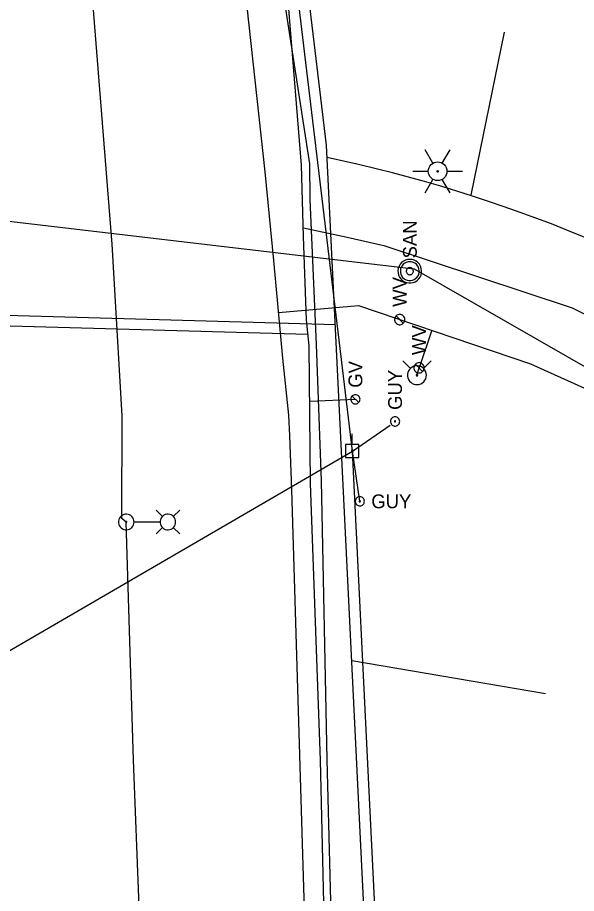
# Model space of a CAD drawing. Extents: x 600849 to 606371, y 330010 to 403088.
# Drawn here: x 604911.1 to 605066.9, y 335171 to 335415.1 of the extents above; entities that cross this region are included whole.
import ezdxf

# ---------------------------------------------------------------- set-up
doc = ezdxf.new("R2010")
doc.units = 0
for name, color, linetype in [('E_LTG', 7, 'Continuous'), ('E_LTG_CID', 7, 'Continuous'), ('E_UTL_EGuyWire', 7, 'Continuous'), ('E_UTL_EPowerPole', 7, 'Continuous'), ('E_UTL_G', 7, 'Continuous'), ('E_UTL_G_UG', 7, 'Continuous'), ('E_UTL_Overhead', 7, 'Continuous'), ('E_UTL_SAN', 7, 'Continuous'), ('E_UTL_SAN_UG', 7, 'Continuous'), ('E_UTL_W', 7, 'Continuous'), ('E_UTL_W_UG', 7, 'Continuous'), ('E_UTL_WHydrant', 7, 'Continuous')]:
    doc.layers.add(name, color=color, linetype=linetype)

msp = doc.modelspace()

# ---------------------------------------------------------------- linework, layer by layer
at = {"layer": 'E_LTG'}
for points in [[(605026.92, 335374.51), (605024.75, 335378.26)], [(605029.52, 335374.51), (605031.68, 335378.26)], [(605021.29, 335372.26), (605025.62, 335372.26)], [(605030.82, 335372.26), (605035.15, 335372.26)], [(605024.75, 335366.26), (605026.92, 335370.01)], [(605031.68, 335366.26), (605029.52, 335370.01)], [(604951.46, 335276.05), (604949.68, 335277.83)], [(604954.51, 335276.05), (604956.28, 335277.83)], [(604943.56, 335274.53), (604943.52, 335274.94), (604943.4, 335275.34), (604943.21, 335275.71), (604942.95, 335276.03), (604942.64, 335276.3), (604942.28, 335276.51), (604941.89, 335276.64), (604941.48, 335276.7), (604941.07, 335276.68), (604940.67, 335276.59), (604940.29, 335276.41), (604939.96, 335276.17), (604939.67, 335275.87), (604939.45, 335275.53), (604939.29, 335275.14), (604939.21, 335274.74), (604939.21, 335274.32), (604939.29, 335273.92), (604939.45, 335273.53), (604939.67, 335273.18), (604939.96, 335272.89), (604940.29, 335272.65), (604940.67, 335272.47), (604941.07, 335272.38), (604941.48, 335272.36), (604941.89, 335272.42), (604942.28, 335272.55), (604942.64, 335272.76), (604942.95, 335273.03), (604943.21, 335273.35), (604943.4, 335273.72), (604943.52, 335274.12), (604943.56, 335274.53)], [(604955.16, 335274.53), (604955.12, 335274.94), (604955, 335275.34), (604954.81, 335275.71), (604954.56, 335276.03), (604954.25, 335276.3), (604953.89, 335276.51), (604953.5, 335276.64), (604953.09, 335276.7), (604952.67, 335276.68), (604952.27, 335276.59), (604951.9, 335276.41), (604951.56, 335276.17), (604951.27, 335275.87), (604951.05, 335275.53), (604950.9, 335275.14), (604950.82, 335274.74), (604950.82, 335274.32), (604950.9, 335273.92), (604951.05, 335273.53), (604951.27, 335273.18), (604951.56, 335272.89), (604951.9, 335272.65), (604952.27, 335272.47), (604952.67, 335272.38), (604953.09, 335272.36), (604953.5, 335272.42), (604953.89, 335272.55), (604954.25, 335272.76), (604954.56, 335273.03), (604954.81, 335273.35), (604955, 335273.72), (604955.12, 335274.12), (604955.16, 335274.53)], [(604941.55, 335274.53), (604941.54, 335274.56), (604941.53, 335274.59), (604941.52, 335274.62), (604941.5, 335274.64), (604941.48, 335274.66), (604941.45, 335274.68), (604941.42, 335274.69), (604941.39, 335274.7), (604941.36, 335274.69), (604941.33, 335274.69), (604941.3, 335274.67), (604941.27, 335274.66), (604941.25, 335274.63), (604941.23, 335274.61), (604941.22, 335274.58), (604941.21, 335274.55), (604941.21, 335274.51), (604941.22, 335274.48), (604941.23, 335274.45), (604941.25, 335274.43), (604941.27, 335274.4), (604941.3, 335274.39), (604941.33, 335274.37), (604941.36, 335274.36), (604941.39, 335274.36), (604941.42, 335274.37), (604941.45, 335274.38), (604941.48, 335274.39), (604941.5, 335274.41), (604941.52, 335274.44), (604941.53, 335274.47), (604941.54, 335274.5), (604941.55, 335274.53)], [(604950.77, 335274.53), (604943.59, 335274.53)], [(604951.46, 335273.01), (604949.68, 335271.23)], [(604954.51, 335273.01), (604956.28, 335271.23)]]:
    msp.add_lwpolyline(points, dxfattribs=at)
for radius in [2.6, 2.6, 2.6, 0.217]:
    msp.add_circle((605028.22, 335372.26), radius, dxfattribs=at)
at = {"layer": 'E_LTG_CID'}
msp.add_lwpolyline([(604969.99, 334606.09), (604967.03, 334670.29), (604963.28, 334734.35), (604962.55, 334735.4), (604960.49, 334790.4), (604957.1, 334864.55), (604955.09, 334914.72), (604953.95, 334915.4), (604951.63, 334970.04), (604948.08, 335053.71), (604947.83, 335094), (604947.12, 335095.14), (604944.98, 335167.5), (604943.36, 335208.16), (604941.38, 335274.53), (604940.11, 335275.5), (604940.27, 335304.13), (604937.49, 335351.94), (604930.99, 335433.63), (604929.86, 335454.1), (604928.76, 335455.44), (604919.1, 335533.39), (604912.51, 335573.53), (604907.99, 335610.09)], dxfattribs=at)
at = {"layer": 'E_UTL_EGuyWire'}
for p, q in [((605004.43, 335294.31), (605014.98, 335301.52)), ((605006.51, 335280.3), (605004.43, 335294.31))]:
    msp.add_line(p, q, dxfattribs=at)
for points in [[(605016.35, 335303.84), (605016.11, 335303.82), (605015.87, 335303.75), (605015.66, 335303.64), (605015.46, 335303.49), (605015.3, 335303.3), (605015.18, 335303.09), (605015.1, 335302.86), (605015.07, 335302.62), (605015.08, 335302.38), (605015.14, 335302.14), (605015.24, 335301.92), (605015.38, 335301.72), (605015.56, 335301.55), (605015.76, 335301.42), (605015.99, 335301.33), (605016.23, 335301.28), (605016.47, 335301.28), (605016.71, 335301.33), (605016.94, 335301.42), (605017.14, 335301.55), (605017.32, 335301.72), (605017.46, 335301.92), (605017.56, 335302.14), (605017.62, 335302.38), (605017.63, 335302.62), (605017.6, 335302.86), (605017.52, 335303.09), (605017.4, 335303.3), (605017.24, 335303.49), (605017.04, 335303.64), (605016.83, 335303.75), (605016.59, 335303.82), (605016.35, 335303.84)], [(605016.35, 335302.72), (605016.32, 335302.72), (605016.29, 335302.71), (605016.26, 335302.69), (605016.24, 335302.68), (605016.22, 335302.65), (605016.2, 335302.63), (605016.19, 335302.6), (605016.19, 335302.57), (605016.19, 335302.54), (605016.2, 335302.51), (605016.21, 335302.48), (605016.23, 335302.45), (605016.25, 335302.43), (605016.28, 335302.42), (605016.3, 335302.41), (605016.33, 335302.4), (605016.37, 335302.4), (605016.4, 335302.41), (605016.42, 335302.42), (605016.45, 335302.43), (605016.47, 335302.45), (605016.49, 335302.48), (605016.5, 335302.51), (605016.51, 335302.54), (605016.51, 335302.57), (605016.51, 335302.6), (605016.5, 335302.63), (605016.48, 335302.65), (605016.46, 335302.68), (605016.44, 335302.69), (605016.41, 335302.71), (605016.38, 335302.72), (605016.35, 335302.72)], [(605007.79, 335280.3), (605007.77, 335280.54), (605007.7, 335280.78), (605007.59, 335280.99), (605007.44, 335281.19), (605007.25, 335281.34), (605007.04, 335281.47), (605006.81, 335281.55), (605006.57, 335281.58), (605006.33, 335281.57), (605006.09, 335281.51), (605005.87, 335281.41), (605005.67, 335281.27), (605005.5, 335281.09), (605005.37, 335280.89), (605005.28, 335280.66), (605005.23, 335280.42), (605005.23, 335280.18), (605005.28, 335279.94), (605005.37, 335279.71), (605005.5, 335279.51), (605005.67, 335279.33), (605005.87, 335279.19), (605006.09, 335279.09), (605006.33, 335279.03), (605006.57, 335279.02), (605006.81, 335279.05), (605007.04, 335279.13), (605007.25, 335279.25), (605007.44, 335279.41), (605007.59, 335279.61), (605007.7, 335279.82), (605007.77, 335280.06), (605007.79, 335280.3)], [(605006.67, 335280.3), (605006.67, 335280.33), (605006.66, 335280.36), (605006.64, 335280.39), (605006.63, 335280.41), (605006.6, 335280.43), (605006.58, 335280.45), (605006.55, 335280.46), (605006.52, 335280.46), (605006.49, 335280.46), (605006.46, 335280.45), (605006.43, 335280.44), (605006.4, 335280.42), (605006.38, 335280.4), (605006.37, 335280.37), (605006.36, 335280.34), (605006.35, 335280.31), (605006.35, 335280.28), (605006.36, 335280.25), (605006.37, 335280.23), (605006.38, 335280.2), (605006.4, 335280.18), (605006.43, 335280.16), (605006.46, 335280.15), (605006.49, 335280.14), (605006.52, 335280.14), (605006.55, 335280.14), (605006.58, 335280.15), (605006.6, 335280.17), (605006.63, 335280.19), (605006.64, 335280.21), (605006.66, 335280.24), (605006.67, 335280.27), (605006.67, 335280.3)]]:
    msp.add_lwpolyline(points, dxfattribs=at)
at = {"layer": 'E_UTL_EPowerPole'}
for points in [[(605004.4, 335296.15), (605004.4, 335299.06)], [(605006.24, 335296.15), (605002.55, 335296.15)], [(605002.55, 335296.15), (605002.55, 335292.46)], [(605004.67, 335294.31), (605004.66, 335294.35), (605004.65, 335294.4), (605004.63, 335294.44), (605004.6, 335294.47), (605004.57, 335294.5), (605004.53, 335294.53), (605004.49, 335294.54), (605004.44, 335294.55), (605004.4, 335294.55), (605004.35, 335294.53), (605004.31, 335294.52), (605004.27, 335294.49), (605004.24, 335294.46), (605004.22, 335294.42), (605004.2, 335294.38), (605004.19, 335294.33), (605004.19, 335294.29), (605004.2, 335294.24), (605004.22, 335294.2), (605004.24, 335294.16), (605004.27, 335294.13), (605004.31, 335294.1), (605004.35, 335294.08), (605004.4, 335294.07), (605004.44, 335294.07), (605004.49, 335294.08), (605004.53, 335294.09), (605004.57, 335294.12), (605004.6, 335294.14), (605004.63, 335294.18), (605004.65, 335294.22), (605004.66, 335294.26), (605004.67, 335294.31)], [(605006.24, 335292.46), (605006.24, 335296.15)], [(605002.55, 335292.46), (605006.24, 335292.46)]]:
    msp.add_lwpolyline(points, dxfattribs=at)
at = {"layer": 'E_UTL_G'}
for points in [[(605005.29, 335310.01), (605005.05, 335309.99), (605004.81, 335309.92), (605004.6, 335309.81), (605004.4, 335309.66), (605004.24, 335309.47), (605004.12, 335309.26), (605004.04, 335309.03), (605004.01, 335308.79), (605004.02, 335308.55), (605004.08, 335308.31), (605004.18, 335308.09), (605004.32, 335307.89), (605004.5, 335307.72), (605004.7, 335307.59), (605004.93, 335307.5), (605005.17, 335307.45), (605005.41, 335307.45), (605005.65, 335307.5), (605005.88, 335307.59), (605006.08, 335307.72), (605006.26, 335307.89), (605006.4, 335308.09), (605006.5, 335308.31), (605006.56, 335308.55), (605006.57, 335308.79), (605006.54, 335309.03), (605006.46, 335309.26), (605006.34, 335309.47), (605006.18, 335309.66), (605005.98, 335309.81), (605005.77, 335309.92), (605005.53, 335309.99), (605005.29, 335310.01)], [(605006.2, 335307.82), (605004.38, 335309.64)]]:
    msp.add_lwpolyline(points, dxfattribs=at)
at = {"layer": 'E_UTL_G_UG'}
for p, q in [((605037.53, 335365.57), (605046.89, 335411)), ((605004.3, 335235.9), (605058.33, 335226.74))]:
    msp.add_line(p, q, dxfattribs=at)
for points in [[(604992.54, 335374.29), (604982.41, 335439.85), (604977.55, 335472.28), (604967.89, 335533.23), (604963.9, 335558.28), (604960.62, 335582.14), (604958.16, 335603.66), (604954.67, 335636.73), (604949.76, 335671.68), (604943.72, 335708.39), (604939.44, 335742.84), (604934.8, 335769.3), (604917.37, 335888.66), (604913.54, 335917.13), (604913.36, 335918.56), (604912.73, 335934.03), (604913.24, 335947.88)], [(604990.22, 335373.94), (604984.89, 335440.46), (604980.73, 335472.71), (604971.32, 335533.67), (604967.23, 335558.65), (604963.42, 335582.81), (604960.7, 335604.2), (604956.77, 335636.76), (604952.03, 335671.62), (604946.45, 335709.05), (604942.07, 335743.65), (604938.29, 335769.61), (604935.75, 335799.26), (604934.37, 335813.01), (604934.01, 335824.97), (604943.83, 335825.34), (604953.01, 335825.14)], [(604990.22, 335373.94), (604984.89, 335440.46), (604980.73, 335472.71), (604971.32, 335533.67), (604967.23, 335558.65), (604963.42, 335582.81), (604960.7, 335604.2), (604956.77, 335636.76), (604952.03, 335671.62), (604946.45, 335709.05), (604942.07, 335743.65), (604938.29, 335769.61), (604935.75, 335799.26), (604934.37, 335813.01), (604934.01, 335824.97), (604943.83, 335825.34), (604953.01, 335825.14)], [(604997.24, 335379.56), (604988.49, 335452.54), (604974.95, 335561.74), (604969.99, 335561.13)], [(605023.72, 334666.34), (605022.29, 334739.51), (605020.22, 334807.28), (605015.57, 334937.18), (605010.93, 335100.97), (604997.24, 335379.56)], [(605013.33, 334743.69), (605010.27, 334787.12), (605009.3, 334815.19), (605006.56, 334858.9), (605003.76, 334923.65), (605002.11, 334959.03), (604999.34, 335036.59), (604998.7, 335074.56), (604997.28, 335132.65), (604995.51, 335208.22), (604992.75, 335285.26), (604992.4, 335323.58), (604991.62, 335330.84), (604990.77, 335354.04), (604990.22, 335373.94)], [(605013.33, 334743.69), (605010.27, 334787.12), (605009.3, 334815.19), (605006.56, 334858.9), (605003.76, 334923.65), (605002.11, 334959.03), (604999.34, 335036.59), (604998.7, 335074.56), (604997.28, 335132.65), (604995.51, 335208.22), (604992.75, 335285.26), (604992.4, 335323.58), (604991.62, 335330.84), (604990.77, 335354.04), (604990.22, 335373.94)], [(605016.63, 334727.49), (605015.37, 334743.6), (605012.34, 334785.87), (605011.57, 334815.96), (605010.04, 334859.35), (605006.31, 334924.5), (605005.36, 334959.77), (605002.04, 335036.89), (605000.68, 335075.43), (604999.39, 335132.92), (604997.4, 335208.34), (604995.8, 335285.97), (604994.4, 335323.96), (604992.67, 335364.38), (604992.54, 335374.29)], [(604990.83, 335356.46), (605003.01, 335353.94)], [(605003.01, 335353.94), (605013.17, 335351.6), (605065.75, 335334.24), (605109.31, 335312.25), (605201.02, 335254.16)], [(605003.01, 335353.94), (605013.17, 335351.6), (605065.75, 335334.24), (605109.31, 335312.25), (605201.02, 335254.16)], [(604736.18, 335331.82), (604751.98, 335334.58), (604818.56, 335334.64), (604819.25, 335334.71), (604999.69, 335329.61)], [(604751.98, 335331.58), (604818.7, 335331.64), (604819.34, 335331.7), (604992.05, 335326.83)], [(604751.98, 335331.58), (604818.7, 335331.64), (604819.34, 335331.7), (604992.05, 335326.83)], [(604992.54, 335308.18), (605005.29, 335308.73)]]:
    msp.add_lwpolyline(points, dxfattribs=at)
msp.add_arc((604911.7, 334972.32), 412.78, 57.31, 78.0163, dxfattribs=at)
at = {"layer": 'E_UTL_Overhead'}
for points in [[(605062.13, 334030.34), (605053.67, 334169.81), (605046.99, 334304.15), (605041.52, 334434.58), (605034.02, 334560.2), (605027.64, 334680.76), (605025.35, 334737.63), (605023.22, 334807.38), (605018.57, 334937.28), (605013.93, 335101.09), (605004.43, 335294.31), (604985.51, 335452.18), (604968.52, 335589.23), (604952.88, 335699.68), (604941.77, 335773.97)], [(604782.82, 335165.57), (605004.43, 335294.31)]]:
    msp.add_lwpolyline(points, dxfattribs=at)
at = {"layer": 'E_UTL_SAN'}
for points in [[(605020.46, 335347.72), (605019.83, 335347.66), (605019.23, 335347.48), (605018.67, 335347.2), (605018.18, 335346.81), (605017.77, 335346.34), (605017.46, 335345.79), (605017.25, 335345.2), (605017.16, 335344.58), (605017.19, 335343.95), (605017.34, 335343.34), (605017.6, 335342.77), (605017.96, 335342.26), (605018.42, 335341.83), (605018.95, 335341.49), (605019.53, 335341.25), (605020.15, 335341.14), (605020.77, 335341.14), (605021.39, 335341.25), (605021.97, 335341.49), (605022.5, 335341.83), (605022.95, 335342.26), (605023.32, 335342.77), (605023.58, 335343.34), (605023.73, 335343.95), (605023.76, 335344.58), (605023.67, 335345.2), (605023.46, 335345.79), (605023.15, 335346.34), (605022.74, 335346.81), (605022.24, 335347.2), (605021.69, 335347.48), (605021.08, 335347.66), (605020.46, 335347.72)], [(605020.46, 335347.06), (605019.96, 335347.01), (605019.48, 335346.87), (605019.03, 335346.64), (605018.64, 335346.33), (605018.31, 335345.95), (605018.06, 335345.52), (605017.89, 335345.04), (605017.82, 335344.55), (605017.85, 335344.05), (605017.96, 335343.56), (605018.17, 335343.1), (605018.46, 335342.69), (605018.83, 335342.35), (605019.25, 335342.07), (605019.72, 335341.89), (605020.21, 335341.79), (605020.71, 335341.79), (605021.2, 335341.89), (605021.67, 335342.07), (605022.09, 335342.35), (605022.45, 335342.69), (605022.75, 335343.1), (605022.95, 335343.56), (605023.07, 335344.05), (605023.1, 335344.55), (605023.02, 335345.04), (605022.86, 335345.52), (605022.61, 335345.95), (605022.28, 335346.33), (605021.89, 335346.64), (605021.44, 335346.87), (605020.96, 335347.01), (605020.46, 335347.06)], [(605020.46, 335345.41), (605020.27, 335345.39), (605020.09, 335345.34), (605019.92, 335345.25), (605019.78, 335345.14), (605019.65, 335345), (605019.56, 335344.83), (605019.5, 335344.65), (605019.47, 335344.47), (605019.48, 335344.28), (605019.52, 335344.1), (605019.6, 335343.93), (605019.71, 335343.77), (605019.85, 335343.64), (605020.01, 335343.54), (605020.18, 335343.47), (605020.36, 335343.44), (605020.55, 335343.44), (605020.74, 335343.47), (605020.91, 335343.54), (605021.07, 335343.64), (605021.21, 335343.77), (605021.32, 335343.93), (605021.39, 335344.1), (605021.44, 335344.28), (605021.45, 335344.47), (605021.42, 335344.65), (605021.36, 335344.83), (605021.27, 335345), (605021.14, 335345.14), (605020.99, 335345.25), (605020.83, 335345.34), (605020.65, 335345.39), (605020.46, 335345.41)]]:
    msp.add_lwpolyline(points, dxfattribs=at)
at = {"layer": 'E_UTL_SAN_UG'}
for p, q in [((604880.14, 335361.64), (605021.69, 335345.12)), ((605021.69, 335345.12), (605290.31, 335190.84))]:
    msp.add_line(p, q, dxfattribs=at)
at = {"layer": 'E_UTL_W'}
msp.add_line((605022.46, 335315.44), (605023.03, 335317.5), dxfattribs=at)
for points in [[(605017.64, 335332.36), (605017.37, 335332.33), (605017.11, 335332.25), (605016.87, 335332.13), (605016.66, 335331.96), (605016.48, 335331.76), (605016.34, 335331.52), (605016.25, 335331.27), (605016.22, 335331), (605016.23, 335330.73), (605016.29, 335330.46), (605016.4, 335330.22), (605016.56, 335330), (605016.76, 335329.81), (605016.99, 335329.66), (605017.24, 335329.56), (605017.5, 335329.51), (605017.78, 335329.51), (605018.04, 335329.56), (605018.29, 335329.66), (605018.52, 335329.81), (605018.72, 335330), (605018.87, 335330.22), (605018.99, 335330.46), (605019.05, 335330.73), (605019.06, 335331), (605019.03, 335331.27), (605018.94, 335331.52), (605018.8, 335331.76), (605018.62, 335331.96), (605018.41, 335332.13), (605018.17, 335332.25), (605017.91, 335332.33), (605017.64, 335332.36)], [(605018.65, 335329.92), (605016.63, 335331.94)], [(605023.03, 335318.93), (605022.76, 335318.9), (605022.5, 335318.82), (605022.26, 335318.7), (605022.05, 335318.53), (605021.87, 335318.33), (605021.73, 335318.09), (605021.64, 335317.84), (605021.61, 335317.57), (605021.62, 335317.3), (605021.68, 335317.03), (605021.79, 335316.79), (605021.95, 335316.57), (605022.15, 335316.38), (605022.38, 335316.23), (605022.63, 335316.13), (605022.89, 335316.08), (605023.17, 335316.08), (605023.43, 335316.13), (605023.68, 335316.23), (605023.91, 335316.38), (605024.11, 335316.57), (605024.26, 335316.79), (605024.38, 335317.03), (605024.44, 335317.3), (605024.45, 335317.57), (605024.42, 335317.84), (605024.33, 335318.09), (605024.19, 335318.33), (605024.01, 335318.53), (605023.8, 335318.7), (605023.56, 335318.82), (605023.3, 335318.9), (605023.03, 335318.93)], [(605024.04, 335316.49), (605022.02, 335318.51)]]:
    msp.add_lwpolyline(points, dxfattribs=at)
at = {"layer": 'E_UTL_W_UG'}
for p, q in [((604983.87, 335332.87), (605006.14, 335334.9)), ((605026.58, 335327.95), (605023.03, 335317.5))]:
    msp.add_line(p, q, dxfattribs=at)
for points in [[(604986.76, 335304.31), (604985.02, 335320.17), (604982.55, 335347.37), (604980.15, 335372.1), (604945.45, 335689.76)], [(605006.14, 335334.9), (605054.16, 335318.57), (605081.35, 335306.35), (605104.71, 335292.8), (605155.95, 335259.74)], [(604987.53, 335283.49), (604986.98, 335298.58), (604986.76, 335304.31)], [(605018.55, 334724.79), (605011.47, 334971.85), (605004.33, 335145.97), (604991.33, 335157.25), (604987.53, 335283.49)]]:
    msp.add_lwpolyline(points, dxfattribs=at)
at = {"layer": 'E_UTL_WHydrant'}
for points in [[(605020.63, 335317.27), (605018.48, 335319.42)], [(605024.3, 335317.27), (605026.44, 335319.42)], [(605025.08, 335315.44), (605025.04, 335315.94), (605024.89, 335316.41), (605024.67, 335316.86), (605024.36, 335317.25), (605023.98, 335317.58), (605023.55, 335317.83), (605023.08, 335317.99), (605022.58, 335318.06), (605022.09, 335318.04), (605021.6, 335317.92), (605021.15, 335317.71), (605020.74, 335317.42), (605020.4, 335317.06), (605020.13, 335316.64), (605019.94, 335316.18), (605019.85, 335315.69), (605019.85, 335315.19), (605019.94, 335314.7), (605020.13, 335314.24), (605020.4, 335313.82), (605020.74, 335313.46), (605021.15, 335313.17), (605021.6, 335312.96), (605022.09, 335312.84), (605022.58, 335312.82), (605023.08, 335312.89), (605023.55, 335313.05), (605023.98, 335313.3), (605024.36, 335313.63), (605024.67, 335314.02), (605024.89, 335314.46), (605025.04, 335314.94), (605025.08, 335315.44)], [(605022.66, 335315.44), (605022.66, 335315.48), (605022.65, 335315.51), (605022.63, 335315.55), (605022.6, 335315.58), (605022.58, 335315.6), (605022.54, 335315.62), (605022.51, 335315.63), (605022.47, 335315.64), (605022.43, 335315.64), (605022.39, 335315.63), (605022.36, 335315.61), (605022.33, 335315.59), (605022.3, 335315.56), (605022.28, 335315.53), (605022.27, 335315.5), (605022.26, 335315.46), (605022.26, 335315.42), (605022.27, 335315.38), (605022.28, 335315.35), (605022.3, 335315.32), (605022.33, 335315.29), (605022.36, 335315.27), (605022.39, 335315.25), (605022.43, 335315.24), (605022.47, 335315.24), (605022.51, 335315.24), (605022.54, 335315.26), (605022.58, 335315.28), (605022.6, 335315.3), (605022.63, 335315.33), (605022.65, 335315.37), (605022.66, 335315.4), (605022.66, 335315.44)]]:
    msp.add_lwpolyline(points, dxfattribs=at)

# ---------------------------------------------------------------- texts
at = {"layer": 'E_UTL_EGuyWire'}
msp.add_text('GUY', height=3.85, rotation=90, dxfattribs=at).set_placement((605018.27, 335305.77))
msp.add_text('GUY', height=3.85, dxfattribs=at).set_placement((605009.72, 335278.37))
at = {"layer": 'E_UTL_G'}
msp.add_text('GV', height=3.85, rotation=90, dxfattribs=at).set_placement((605007.21, 335311.94))
at = {"layer": 'E_UTL_SAN'}
msp.add_text('SAN', height=3.849, rotation=90, dxfattribs=at).set_placement((605022.4, 335347.98))
at = {"layer": 'E_UTL_W'}
for p in [(605019.56, 335334.49), (605024.95, 335321.06)]:
    msp.add_text('WV', height=3.85, rotation=90, dxfattribs=at).set_placement(p)

doc.saveas('drawing.dxf')
